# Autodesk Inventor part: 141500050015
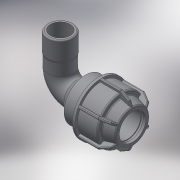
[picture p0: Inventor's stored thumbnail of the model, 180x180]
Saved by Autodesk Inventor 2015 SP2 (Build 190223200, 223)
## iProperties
Created: 2017-08
Part Number: 141500050015
Material: Generic
Description: L.14 90° ELBOW FEMALE ADAPTOR (SILVER) 50-1.1/2"
Document SubType Name: Modeling
Designer: KIM
Density: 1 g/cm^3
Appearance: Default
Author: KIM
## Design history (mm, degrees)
derived "141500.ipt"
feature "Solid1::141500.ipt"
feature "Solid2::141500.ipt"
tag "TaggingFeature1"
body "Solid1"
body "Solid2"
other parameters: "d2" = 74, "d4" = 15 deg, "d5" = 48.84, "d6" = 16.1172, "d10" = 92, "d16" = 51, "d17" = 3.7, "d24" = 3.7, "d25" = 82.8, "d26" = 69, "d27" = 3.7, "d28" = 135 deg, "d29" = 2.22, "d31" = 2.5, "d46" = 150 deg, "d49" = 4.6, "d50" = 0, "d58" = 1.5, "d61" = 360 deg, "d63" = 45, "d94" = 79, "d95" = 44.845, "d96" = 58.2985, "d97" = 25, "d98" = 35.876, "d99" = 52.46865, "d100" = 135 deg, "d108" = 2.5, "d112" = 32.5, "d113" = 102, "d114" = 75.48, "d115" = 52.46865, "d116" = 45 deg, "d117" = 0, "d118" = 0, "G_" = 44.845, "E_" = 92, "A_" = 102, "l_" = 74, "l_2" = 25, "A_1" = 79
